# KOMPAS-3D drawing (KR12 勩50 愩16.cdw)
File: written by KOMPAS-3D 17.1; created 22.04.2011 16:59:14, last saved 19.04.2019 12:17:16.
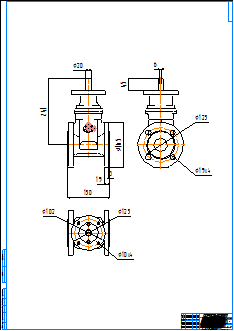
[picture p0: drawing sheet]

Title block, sheet 1: name: KR12 Ду50 Ру16; material: Внимание! Данный продукт является объектом авторского права ООО «Торговый Дом АДЛ». / Запрещается изменение, копирование, распространение / (в том числе путем копирования на другие сайты и ресурсы в Интернете) / или любое иное использование информации и объектов без предварительного / согласия правообладателя (ООО «Торговый Дом АДЛ»).; scale: 1:1; sheets: 1; organisation: ООО "Торговый дом АДЛ"; sheet format: A0; stored path: \\adlc.lan\data\АДЛ_ПКД\3D-модели\ADL production\Клиновые задвижки серии KR ГРАНАР\Клиновые задвижки KR12\KOMPAS 2D\KR12 Ду50 Ру16.cdw

Views: Спереди 4, Проекционный вид 5, Проекционный вид 6
Dimensions and other numbers on the sheet: 150; 19; 3; 165; 241; 20; 125; 102; 10; 45; 6; 1:1; 1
